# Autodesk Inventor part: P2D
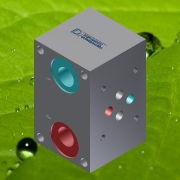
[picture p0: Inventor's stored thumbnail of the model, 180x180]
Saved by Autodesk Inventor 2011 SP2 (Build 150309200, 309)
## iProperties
Created: 2013-12
Part Number: P2D
Document SubType Name: Modeling
Designer: dorohin
Density: 1 g/cm^3
Author: dorohin
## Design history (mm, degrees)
derived "1560121-06.ipt"
feature "Solid1::1560121-06.ipt" dims "d0" = 10
tag "Элемент создания маркировки1"
node "Твердое тело1"
